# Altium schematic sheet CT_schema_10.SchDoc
size 226 x 144 mm
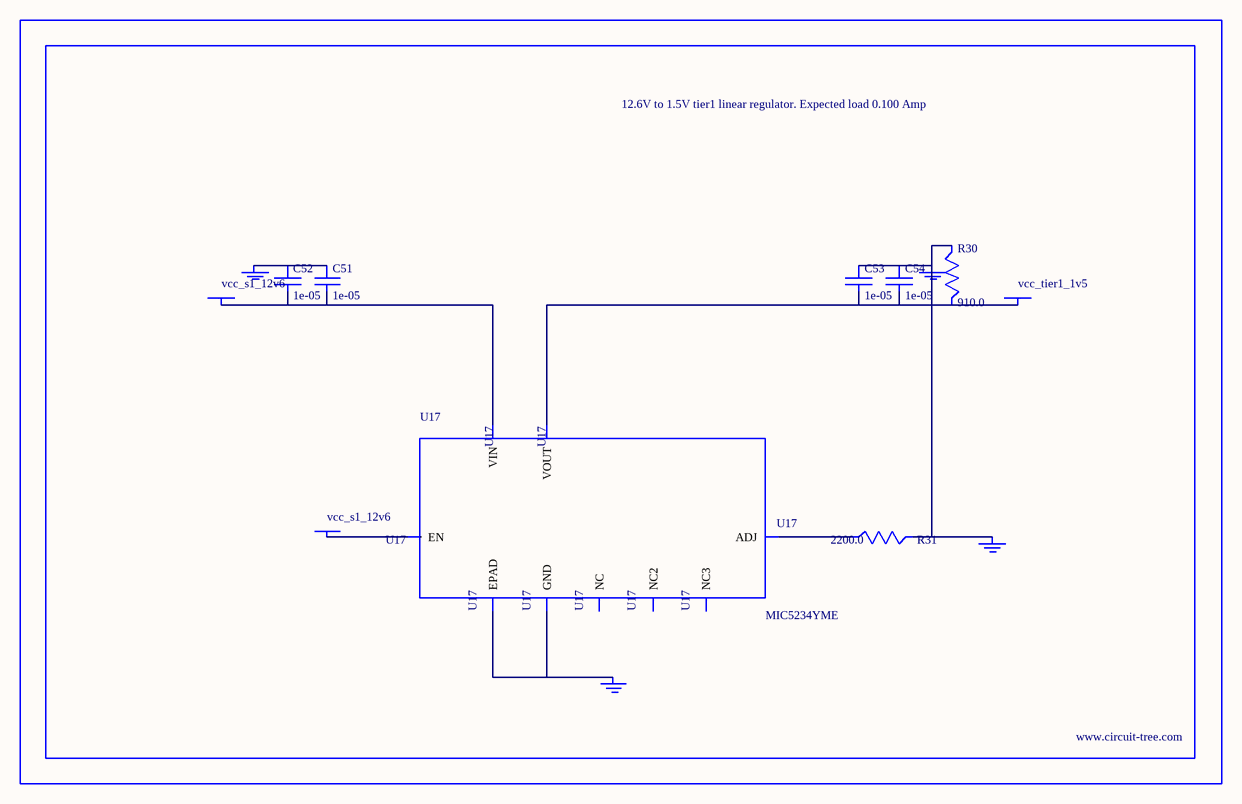
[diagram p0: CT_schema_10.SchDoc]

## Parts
BORDER9  (no value)
C51  1e-05  [C1210]
C52  1e-05  [C1210]
C53  1e-05  [C1210]
C54  1e-05  [C1210]
GND_INSTANCE_9_0  (no value)
GND_INSTANCE_9_1  (no value)
GND_INSTANCE_9_2  (no value)
GND_INSTANCE_9_3  (no value)
POWER_INSTANCE_9_0  vcc_tier1_1v5
POWER_INSTANCE_9_1  vcc_s1_12v6
POWER_INSTANCE_9_2  vcc_s1_12v6
R30  910.0  [R0603]
R31  2200.0  [R0603]
U17  MIC5234YME  [SOIC-8_EP]

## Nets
NetC51_1: C51.1 C52.1 GND_INSTANCE_9_3.0(GND)
NetC51_2: C51.2 C52.2 POWER_INSTANCE_9_2.0(PWR) U17.8(VIN)
NetC53_1: C53.1 C54.1 GND_INSTANCE_9_0.0(GND) GND_INSTANCE_9_1.0(GND) R30.1 R31.2
NetC53_2: C53.2 C54.2 POWER_INSTANCE_9_0.0(PWR) R30.2 U17.1(VOUT)
NetGND_INSTANCE_9_2_0: GND_INSTANCE_9_2.0(GND) U17.7(GND) U17.EPAD
NetPOWER_INSTANCE_9_1_0: POWER_INSTANCE_9_1.0(PWR) U17.5(EN)
NetR31_1: R31.1 U17.4(ADJ)

Not connected (* = marked no-connect by the designer): U17 2(NC) 3(NC2) 6(NC3)

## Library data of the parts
BORDER9 = BORDER_PAGE9
C51-C54 = C1210C106K5PACTU
GND_INSTANCE_9_0-GND_INSTANCE_9_3 = GND
POWER_INSTANCE_9_0-POWER_INSTANCE_9_2 = PWR
R30 = RC0603JR-07910RL
R31 = RC0603JR-072K2L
